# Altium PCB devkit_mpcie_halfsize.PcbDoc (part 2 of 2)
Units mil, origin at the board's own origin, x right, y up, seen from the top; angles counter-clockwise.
Board outline 1185.07 x 1313.97 mil, 4 copper layers (Top Layer, Mid-Layer 1, Mid-Layer 2, Bottom Layer), stack 34.6 mil thick; 83 components, 51 nets, 256 pads, 210 vias.
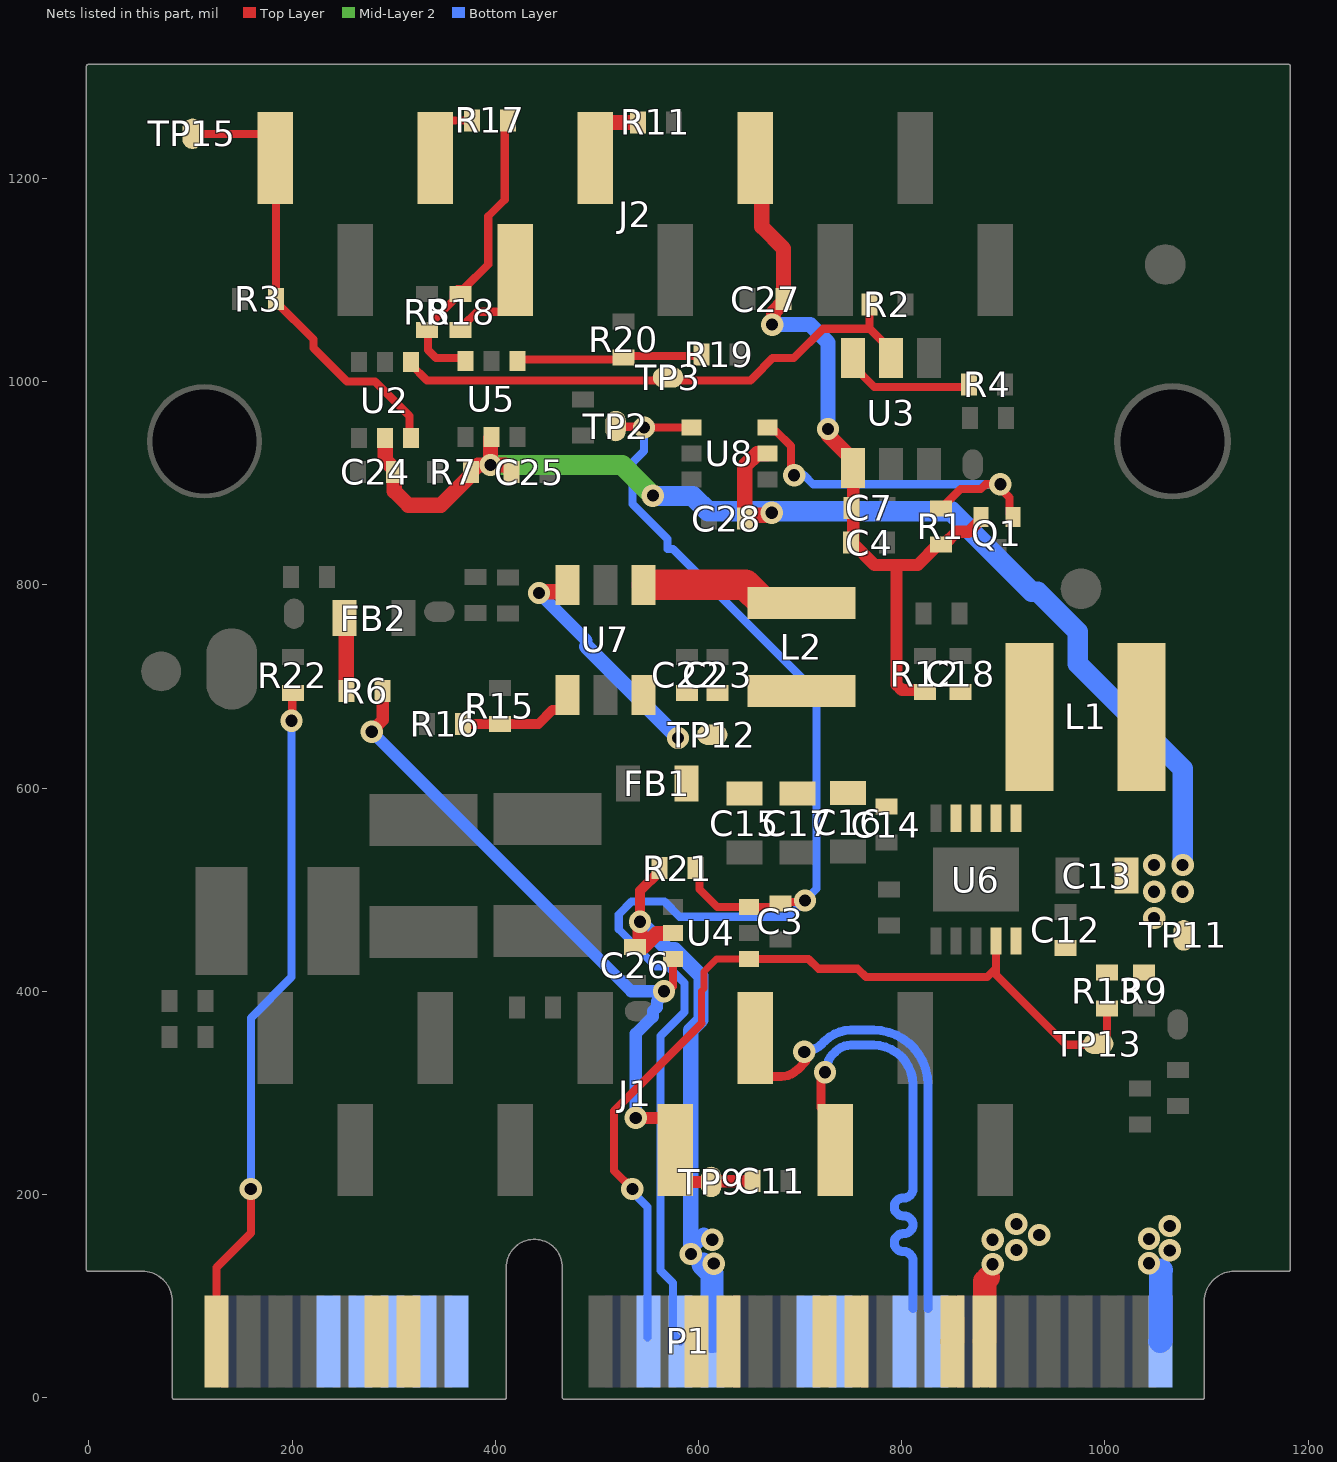
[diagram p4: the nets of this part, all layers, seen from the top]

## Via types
v1: diameter 22, hole 12, Top Layer to Bottom Layer, 210 vias

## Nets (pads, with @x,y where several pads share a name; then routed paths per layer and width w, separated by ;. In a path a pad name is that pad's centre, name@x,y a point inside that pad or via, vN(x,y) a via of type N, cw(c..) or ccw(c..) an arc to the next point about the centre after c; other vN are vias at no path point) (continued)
NetJ2_6: J2.6 R11.2 | length 67.8
  Top Layer w15: J2.6@498.23,1227.15 498.23,1251.35 502.09,1255.22 R11.2@540.21,1255.22
NetJ2_7: J2.7 R18.1 | length 97.9
  Top Layer w8: R18.1@365.85,1055.74 368.8,1055.74 381.89,1068.83 405.97,1068.83 419.49,1082.35 419.49,1094.89 J2.7@419.49,1109.91 ; J2.7@417.21,1112.19 419.49,1114.47 J2.7@419.49,1116.91
NetJ2_8: J2.8 R17.1 | length 27
  Top Layer w8: J2.8@350.19,1257.15 R17.1@377.18,1257.15
NetL1_2: L1.2 U6.1 U6.2
NetL2_2: L2.2 U7.1 | length 159.6
  Top Layer w30: U7.1@548.96,799.95 646.18,799.95 663.82,782.31 L2.2@701.22,782.31
NetQ1_1: Q1.1 R1.1 U8.6 | length 380.4
  Top Layer w8: U8.6@667.72,954.96 671.59,951.09 676.45,951.09 690.9,936.63 690.9,911.1 v1(694,908) ; R1.1@838.54,875.08 857.83,894.37 877.76,894.37 882.39,899 v1(897.03,899) 897.03,895.21 906.05,886.19 Q1.1@906.05,872.59 ; Q1.1@906.05,872.59 906.05,870.03 Q1.1@909.33,866.75 909.33,869.31 Q1.1@906.05,872.59
  Bottom Layer w8: v1(694,908) 703.85,908 712.85,899 v1(897.03,899)
NetR2_2: R2.2 TP3.1 U2.1 U3.5 | length 546.1
  Top Layer w8: U2.1@316.73,1019.18 316.73,1017.21 332.61,1001.33 TP3.1@558.81,1001.33 ; TP3.1@558.81,1004.19 TP3.1@558.81,1001.33 ; R2.2@768.21,1076.22 768.21,1052.57 768.73,1052.06 ; U3.5@789.54,1023.37 789.54,1031.24 768.73,1052.06 ; TP3.1@558.81,1001.33 651.02,1001.33 653.88,1004.19 672.88,1023.19 693.67,1023.19 722.54,1052.06 736.6,1052.06 768.73,1052.06
NetR4_2: R4.2 U3.6 | length 137.2
  Top Layer w8: U3.6@752.14,1027.5 750.39,1025.75 750.39,1017.25 772.95,994.69 863.68,994.69 R4.2@866.21,997.22
NetR8_2: R8.2 R17.2 R18.2 U5.3 | length 305.9
  Top Layer w8: U5.3@370.39,1020.17 367.37,1023.19 341.71,1023.19 333.66,1031.24 333.66,1050.22 R8.2@332.76,1051.12 335.71,1051.12 339.59,1054.99 339.59,1060.91 359.02,1080.34 359.02,1087.3 362.89,1091.18 368.8,1091.18 392.97,1115.34 392.97,1162.87 409.2,1179.09 409.2,1253.74 R17.2@412.61,1257.15
NetR15_1: R15.1 R16.2 U7.4 | length 125.1
  Top Layer w10: R16.2@368.18,663.15 442.44,663.15 456.28,676.99 464.16,676.99 470.97,683.8 U7.4@470.97,691.68 ; R15.1@401.38,663.05 R15.1@404.33,663.05 R15.1@407.28,663.05
NetR19_2: R19.2 R20.2 U5.1 | length 184.5
  Top Layer w8: U5.1@421.57,1020.17 423.39,1022 524.33,1022 R20.2@526.15,1023.82 ; R20.2@527.66,1025.34 530.79,1025.34 601.31,1025.34 R19.2@602.82,1026.85 ; R20.2@530.79,1022 R20.2@532.61,1023.82
ON_OFF: J2.10 R3.2 TP15.1 U2.6 | length 446.6
  Top Layer w8: TP15.1@101.83,1243.96 169.75,1243.96 183.27,1230.44 J2.10@183.27,1220.15 184.22,1219.19 184.22,1078.55 221.02,1041.76 221.02,1033.26 253.94,1000.34 281.41,1000.34 315.53,966.22 315.53,945.57 U2.6@316.73,944.38 ; J2.10@181.79,1238.37 J2.10@183.27,1239.85
PER0_N: P1.23
PER0_P: P1.25
PERST#: C3.1 P1.22 R21.1 TP2.1 U4.3 U8.1 | length 1429.7
  Top Layer w8: TP2.1@518.39,956.37 519.09,955.67 545.55,955.67 v1(546.25,954.96) U8.1@592.91,954.96 ; R21.1@597.06,521.26 600.94,517.39 600.94,500.43 618.41,482.96 U4.3@649.47,482.96 ; U4.3@658.23,482.75 676.67,482.75 C3.1@680.54,486.63 681.91,488 v1@706.05,488
  Bottom Layer w8: v1(546.25,954.96) 546.25,931.61 535,920.36 535,879.58 569.45,845.12 569.45,835.29 574.99,835.29 716.22,694.07 716.22,500.91 v1(704.68,489.37) 688.68,473.37 581.36,473.37 566.36,488.37 534.05,488.37 521.39,475.71 521.39,461.03 557.84,424.57 569.71,424.57 586,408.28 586,379.47 562.66,356.13 562.66,125.1 574.99,112.76 574.99,62.56 P1.22@582.07,55.49
PET0_N: P1.31
PET0_P: P1.33
REFCLK_N: P1.11
REFCLK_P: P1.13
SKY_USB_N: J1.8 P1.36 | length 423
  Top Layer w8.8: J1.8@720.5,285.37 720.5,310.99 cw(c733.76,310.99) v1(724.39,320.37)
  Bottom Layer w8.8: v1(724.39,320.37) ccw(c718.29,326.47) 726.91,326.47 cw(c742.27,326.47) 731.41,337.33 734.78,340.7 cw(c750,325.48) 750,347 772,347 cw(c772,308.06) 810.94,308.06 810.94,206 810.94,205.4 cw(c802.14,205.4) 802.14,196.6 801.37,196.6 ccw(c801.37,187.8) 792.57,187.8 ccw(c801.37,187.8) 801.37,179 802.14,179 cw(c802.14,170.2) 810.94,170.2 cw(c802.14,170.2) 802.14,161.4 801.37,161.4 ccw(c801.37,152.6) 792.57,152.6 ccw(c801.37,152.6) 801.37,143.8 802.14,143.8 cw(c802.14,135) 810.94,135 P1.36@810.94,88
SKY_USB_P: J1.7 P1.38 | length 438.1
  Top Layer w7.7: J1.7@654.39,316.12 J1.7@654.39,316.37 ; v1@705.5,330.98 ccw(c696.11,340.37) v1@709.39,340.37
  Top Layer w8.8: J1.7@669.39,316.12 681.08,316.12 ccw(c681.08,339.18) 697.38,322.86 v1@705.5,330.98
  Bottom Layer w7.7: v1(704.07,340.37) cw(c710.67,333.77) v1@710.67,343.11
  Bottom Layer w8.8: v1(704.07,340.37) cw(c710.17,334.27) 710.17,342.9 ccw(c710.17,357.1) 720.21,347.06 724.35,351.19 cw(c749.95,325.59) 749.95,361.8 772.1,361.8 cw(c772.1,308.16) 825.74,308.16 825.74,206 825.74,205.4 P1.38@825.74,88
SMB_CLK: P1.30
SMB_DATA: P1.32
UIM_CLK: P1.12
UIM_DATA: P1.10
UIM_PWR: P1.8
UIM_RESET: P1.14
UIM_VPP: P1.16
VCC_3V3: C12.1 C13.1 C24.1 C25.1 C26.1 C28.1 L1.1 P1.24 P1.39 P1.41 P1.52 R7.2 R9.2 R13.2 R21.2 TP11.1 U2.5 U4.5 U5.5 U6.10 U8.5 | length 1989.8
  Top Layer w10: v1(542.33,468.37) 542.33,499.01 561.63,518.31 R21.2@561.63,521.26
  Top Layer w15: U2.5@291.14,944.38 291.51,944 291.51,922.86 300.11,914.26 C24.1@300.11,911.31 300.48,910.93 300.48,892.28 314.27,878.5 346.41,878.5 376.04,908.13 R7.2@376.04,911.09 382.93,917.97 v1(395.26,917.97) ; U5.5@395.98,945.37 395.26,944.65 v1(395.26,917.97) ; C25.1@415.9,911.83 409.76,917.97 v1(395.26,917.97) ; v1(542.33,468.37) 542.41,468.29 542.41,443.7 542.49,443.63 545.44,443.63 558.81,457 574.29,457 U4.5@574.67,457.37 ; U8.5@667.72,929.37 667.34,929 657.54,929 645.38,916.83 645.38,865.46 C28.1@645.62,865.22 645.62,868.17 645.99,868.54 667.58,868.54 670.03,871 v1(671.93,871)
  Top Layer w23: P1.39@849.78,55.49 850.09,55.8 P1.39@850.09,77.37 ; P1.41@881.28,55.49 881.59,55.8 881.59,114.73 885.39,118.53
  Mid-Layer 2 w20: v1(395.26,917.97) 524.89,917.97 v1(555,887.86)
  Bottom Layer w15: v1(542.33,468.37) 569.63,441.07 576.54,441.07 602.5,415.12 602.5,371.85 592.39,361.74 v1(592.39,141.37) ; v1@593.73,148.71 v1@605.17,160.16
  Bottom Layer w20: v1(555,887.86) 555.38,887.48 594.17,887.48 609.28,872.37 848.58,872.37 927.73,793.21 933.84,793.21 973.14,753.91 973.14,722.52 1076.39,619.28 v1(1076.39,524.37)
  Bottom Layer w23: v1@604.39,131.37 613.25,122.51 613.25,55.8 P1.24@613.56,55.49 ; P1.52@1054.51,55.49 1054.82,55.8 1054.82,124.8 1055.39,125.37
  other v1: 889.39,131.37 615,132 1043.39,132.37 912.77,145.38 1063.69,145 613.39,155.43 889.39,155.43 1043.39,156.35 935.25,160.16 1063.69,169 912.77,171 1048.39,472.12 1048.39,498 1076.39,498 1048.39,524.37
VCC_4V0: C4.1 C7.1 C14.1 C15.1 C16.1 C17.1 C18.2 C22.1 C23.1 C27.1 FB1.1 J2.4 L2.1 Q1.2 R1.2 R12.2 TP12.1 U3.1 U6.3 U6.4 U7.3 U7.6 | length 990.5
  Top Layer w12: U3.1@752.14,915.1 752.14,840.68 773.12,819.7 794.38,819.7 ; R12.2@822.97,694.69 821.1,696.56 800.11,696.56 794.95,701.72 794.95,819.12 794.38,819.7 ; Q1.2@877.83,866.75 877.83,864.19 865.96,852.32 854.16,852.32 841.49,839.65 R1.2@838.54,839.65 835.59,839.65 815.64,819.7 794.38,819.7
  Top Layer w15: v1(443,792) 444.34,793.34 466.66,793.34 470.97,797.65 U7.3@470.97,799.95 U7.3@468.66,797.64 ; J2.4@655.71,1220.15 662.19,1213.67 662.19,1152.57 683.65,1131.11 C27.1@683.65,1081.22 683.65,1078.26 673.73,1068.35 673.73,1057.53 v1(672.39,1056.19) ; v1(727.39,953.37) 727.39,947.73 752.14,922.98 U3.1@752.14,915.1
  Bottom Layer w12: v1(443,792) 489.8,745.2 489.8,739.26
  Bottom Layer w15: 489.8,739.26 v1(579.81,649.25) ; v1(672.39,1056.19) 709.87,1056.19 727.39,1038.67 v1(727.39,953.37)
VCC_5V0: FB2.2 R6.2 | length 72.4
  Top Layer w15: FB2.2@251.43,767.22 253.32,765.32 253.32,696.16 R6.2@253.7,695.78
VCC_VUSB: C11.1 J1.6 R6.1 TP9.1 U4.6 | length 777.1
  Top Layer w8: v1(566,400) 569.79,400 574.47,404.69 574.67,404.69 U4.6@574.67,431.78
  Top Layer w12: v1(278.3,655.4) 278.3,656.13 289.13,666.96 R6.1@289.13,695.78 ; v1(538.19,275.37) 565.62,275.37 577.14,263.85 J1.6@577.14,243.84 577.14,223.89 588.66,212.37 TP9.1@612.39,212.37 612.96,212.95 652.53,212.95 C11.1@653.11,213.52
  Bottom Layer w12: v1(278.3,655.4) 533.7,400 v1(566,400) 566,397.29 559,390.29 559,384.29 555,380.29 555,375 538.19,358.19 v1(538.19,275.37)
W_DISABLE#: P1.20 R13.1 TP13.1 U4.1 U6.9 | length 915.7
  Top Layer w7: 602.82,368.29 602.82,400.23 605.42,402.83 605.42,419.45 617.76,431.78 U4.1@649.47,431.78
  Top Layer w8: v1(534.82,205.4) 516.86,223.36 516.86,282.33 602.82,368.29 ; U4.1@649.47,431.78 708.35,431.78 717.98,422.16 756.5,422.16 764.65,414.01 884.09,414.01 892.63,422.54 ; U6.9@892.63,449.49 892.63,422.54 ; R13.1@1001.85,382.98 1001.85,356.83 1000.68,355.67 1000.68,353.91 995.14,348.37 TP13.1@993.39,348.37 992.39,347.37 961.53,347.37 892.63,416.27 892.63,422.54
  Bottom Layer w8: v1(534.82,205.4) 534.82,202.55 549.66,187.71 P1.20@549.66,59.32
WAKE: P1.1 R22.2 | length 669.3
  Top Layer w8: P1.1@125.37,55.49 125.37,128.33 159.29,162.24 v1(159.29,205.4) ; v1(199.39,666.2) 200.04,666.86 200.04,692.92 R22.2@200.7,693.57
  Bottom Layer w8: v1(159.29,205.4) 159.29,373.87 199.39,413.97 v1(199.39,666.2)
pads on no net: Fiducial1.Fiducial Fiducial2.Fiducial Fiducial3.Fiducial J1.2 J1.3 J2.2 J2.9 P1.2 P1.6 P1.17 P1.19 P1.28 P1.45 P1.47 P1.48 P1.49 P1.51 U2.4 U6.5 U6.8 U8.4

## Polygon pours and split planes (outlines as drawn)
GND on Top Layer "GND_L01_P042" (solid, remove dead copper, pour order 42): 0.19,1307.84 1181.19,1307.84 1181.19,123.82 1127.16,123.82 ccw(c1127.16,92.84) 1096.19,92.84 cw(c1081.19,92.84) 1081.19,77.84 507.19,77.84 cw(c507.19,115.84) 469.19,115.84 469.19,124.71 ccw(c438.19,124.71) 438.19,155.71 ccw(c438.19,127.71) 410.19,127.71 410.19,97.84 cw(c390.19,97.84) 390.19,77.84 100.19,77.84 cw(c100.19,92.84) 85.19,92.84 ccw(c54.14,92.84) 54.14,123.88 50.19,123.88 0.19,123.82
VCC_3V3 on Top Layer "VCC_3V3_L01_P020" (solid, pour order 20): 1012.04,737.74 1012.04,566.95 992.14,547.06 992.14,484.06 972.42,464.34 909.42,464.34 907.42,462.34 907.42,439.34 935.39,411.37 1090.96,411.37 1094.47,414.88 1093.94,652.48 1059.39,739.4
NetC20_1 on Top Layer "NETC20_1_L01_P002" (solid, pour order 2): 298.87,784.62 459.4,784.62 517.91,726.1 517.91,676.14 482.32,711.74 450.03,711.74 433.15,694.87 361.13,694.87 298.87,757.12
NetL2_2 on Top Layer "NETL2_2_L01_P000" (solid, pour order 0): 556.83,828.8 707.7,828.8 746.88,789.62 723.5,766.25 648.6,766.25 634.31,780.54 556.33,780.54 541.23,805.13
VCC_4V0 on Top Layer "VCC_4V0_L01_P004" (solid, pour order 4): 877.84,571.25 877.83,686.72 847.42,710.88 534.82,710.88 534.82,675.37 575.65,604.46 600.63,569.37 806.67,569.37 822.92,586.43 844.22,586.31 850.04,571.25
NetC5_1 on Top Layer "NETC5_1_L01_P014" (solid, pour order 14): 139.39,305.37 104.39,340.37 104.39,572.54 168.21,636.37 351.1,636.37 526.15,636.37 539.36,618.12 539.36,575.38 501.35,537.37 214.39,537.37 200.39,523.37 200.39,305.37
NetL1_2 on Top Layer "NETL1_2_L01_P016" (solid, pour order 16): 950.2,692.91 950.2,579.96 931.75,568.49 886.87,568.49 886.87,594.17 924.14,696.63 941.64,714.05
VCC_3V3 on Top Layer "VCC_3V3_L01_P012" (solid, pour order 12): 891.39,81.37 848.39,81.37 838.39,91.37 838.39,122.37 852.4,138.73 889.76,182.37 921.87,182.37 941.54,162.71 941.54,149.77 891.45,99.69
GND on Bottom Layer "GND_L04_P040" (solid, remove dead copper, pour order 40): 0,1308.15 1181,1308.15 1181,124.13 1126.98,124.13 ccw(c1126.98,93.15) 1096,93.15 cw(c1081,93.15) 1081,78.15 507,78.15 cw(c507,116.15) 469,116.15 469,125.02 ccw(c438,125.02) 438,156.02 ccw(c438,128.02) 410,128.02 410,98.15 cw(c390,98.15) 390,78.15 100,78.15 cw(c100,93.15) 85,93.15 ccw(c53.96,93.15) 53.96,124.19 50,124.19 0,124.13
no net on Bottom Layer "NONET_L04_P046" (solid, pour order 46): -4423.12,-4763
VCC_3V3 on Bottom Layer "VCC_3V3_L04_P032" (solid, pour order 32): 1063.39,90.37 1076.39,103.37 1076.39,175.33 1068.71,183 1048.39,183 1024,158.61 1024,133.64 1043.39,114.25 1043.39,81.37 1049.39,75.37
VCC_3V3 on Bottom Layer "VCC_3V3_L04_P028" (solid, pour order 28): 618.39,172.37 587.39,172.37 575.39,160.37 575.39,132.37 597.39,110.37 625.39,110.37 628.39,113.37 628.39,162.37
GND on Mid-Layer 1 "GND_L02_P036" (solid, pour order 36): -0.61,1310.37 1180.39,1310.37 1180.39,126.35 1126.36,126.35 ccw(c1126.36,95.37) 1095.39,95.37 cw(c1080.39,95.37) 1080.39,80.37 506.39,80.37 cw(c506.39,118.37) 468.39,118.37 468.39,127.24 ccw(c437.39,127.24) 437.39,158.24 ccw(c437.39,130.24) 409.39,130.24 409.39,100.37 cw(c389.39,100.37) 389.39,80.37 99.39,80.37 cw(c99.39,95.37) 84.39,95.37 ccw(c53.34,95.37) 53.34,126.41 49.39,126.41 -0.61,126.35
VCC_3V3 on Mid-Layer 1 "VCC_3V3_L02_P034" (solid, pour order 34): 1090.99,154.15 1050.22,113.37 593.39,113.37 577.39,129.37 577.39,166.94 594.45,184 769.02,184 869.39,284.37 869.39,399.88 979.3,509.79 1003.82,537.37 1090.99,537.37
GND on Mid-Layer 2 "GND_L03_P038" (solid, pour order 38): -0.61,1310.37 1180.39,1310.37 1180.39,126.35 1126.36,126.35 ccw(c1126.36,95.37) 1095.39,95.37 cw(c1080.39,95.37) 1080.39,80.37 506.39,80.37 cw(c506.39,118.37) 468.39,118.37 468.39,127.24 ccw(c437.39,127.24) 437.39,158.24 ccw(c437.39,130.24) 409.39,130.24 409.39,100.37 cw(c389.39,100.37) 389.39,80.37 99.39,80.37 cw(c99.39,95.37) 84.39,95.37 ccw(c53.34,95.37) 53.34,126.41 49.39,126.41 -0.61,126.35

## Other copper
Top Layer:
  pour cut-out: 957.78,575.37 961.53,575.37 939.69,553.53 919.55,553.53
  pour cut-out: 1012.04,570.16 950.2,570.16 950.2,750.96 1012.04,750.96
  pour cut-out: 637.63,711.75 637.63,761.4 642.48,766.25 764.81,766.25 764.81,711.75
  pour cut-out: 362.85,77 362.85,105.76 395.55,105.76
  pour cut-out: 1055.57,105.76 1088,105.76 1088,93 1054.39,93
  pour cut-out: 678.23,1170.07 690.93,1157.37 720.69,1157.37
  pour cut-out: 813.09,721.68
Bottom Layer:
  pour cut-out: 95.44,76.75 95.44,105.52 128.15,105.52
  pour cut-out: 506,76.89 506,105.39 473.59,105.39
  pour cut-out: 363.44,77 363.44,105.76 396.15,105.76

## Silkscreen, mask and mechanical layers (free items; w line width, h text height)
Top Overlay:
  drawing of 1300 lines, arcs and shapes, not listed
  text "1002580REVA" at 58.39,162.37 h30 r90
Mechanical 2 - Board Outline:
  lines w3.94: -0.61,126.35 -0.61,1310.37 ; -0.61,126.35 52.54,126.35 ; -0.61,126.35 -0.61,1310.37 ; -0.61,126.35 52.54,126.35 ; -0.61,1310.37 1180.49,1310.37 ; -0.61,1310.37 1180.49,1310.37 ; 52.54,126.35 cw(c52.54,94.86) 84.03,94.86 ; 52.54,126.35 cw(c52.54,94.86) 84.03,94.86 ; 84.03,0.37 84.03,94.86 ; 84.03,0.37 408.84,0.37 ; 84.03,0.37 408.84,0.37 ; 84.03,0.37 84.03,94.86 ; 408.84,0.37 408.84,128.32 ; 408.84,0.37 408.84,128.32 ; 408.84,128.32 cw(c438.36,128.32) 467.89,128.32 ; 408.84,128.32 cw(c438.36,128.32) 467.89,128.32 ; 467.89,0.37 467.89,128.32 ; 467.89,0.37 1095.84,0.37 ; 467.89,0.37 467.89,128.32 ; 467.89,0.37 1095.84,0.37 ; 1095.84,0.37 1095.84,94.86 ; 1095.84,0.37 1095.84,94.86 ; 1095.84,94.86 cw(c1127.34,94.86) 1127.34,126.35 ; 1095.84,94.86 cw(c1127.34,94.86) 1127.34,126.35 ; 1127.34,126.35 1180.49,126.35 ; 1127.34,126.35 1180.49,126.35 ; 1180.49,126.35 1180.49,1310.37 ; 1180.49,126.35 1180.49,1310.37
Drill Drawing:
  drawing of 1074 lines, arcs and shapes, not listed
  text "Symbol" at 10597.5,5502.5 h72
  text "Count" at 11103.38,5502.5 h72
  text "Hole Size" at 11693.22,5502.5 h72
  text "Plated" at 12842.88,5502.5 h72
  text "Hole Type" at 13348.76,5502.5 h72
  text "Drill Layer Pair" at 14082.56,5502.5 h72
  text "Via/Pad" at 15582.11,5502.5 h72
  text "Pad Shape" at 16171.96,5502.5 h72
  text "Template" at 16917.76,5502.5 h72
  text "Description" at 17567.59,5502.5 h72
  text "Hole Tolerance (+)" at 18421.35,5502.5 h72
  text "Hole Tolerance (-)" at 19754.96,5502.5 h72
  text "2" at 11103.38,5352.5 h60
  text "2.600mm (102.36mil)" at 11693.22,5352.5 h60
  text "PTH" at 12842.88,5352.5 h60
  text "Round" at 13348.76,5352.5 h60
  text "Top Layer - Bottom Layer" at 14082.56,5352.5 h60
  text "Pad" at 15582.11,5352.5 h60
  text "Rounded" at 16171.96,5352.5 h60
  text "(Mixed)" at 16917.76,5352.5 h60
  text "210" at 11103.38,5202.5 h60
  text "0.305mm (12.00mil)" at 11693.22,5202.5 h60
  text "PTH" at 12842.88,5202.5 h60
  text "Round" at 13348.76,5202.5 h60
  text "Top Layer - Bottom Layer" at 14082.56,5202.5 h60
  text "Via" at 15582.11,5202.5 h60
  text "Rounded" at 16171.96,5202.5 h60
  text "v56h30" at 16917.76,5202.5 h60
  text "212 Total" at 11103.38,5052.5 h60
  text "Layer" at 10577.5,4657.5 h60
  text "Name" at 10987.41,4657.5 h60
  text "Material" at 11917.16,4657.5 h60
  text "Thickness" at 12776.92,4657.5 h60
  text "Constant" at 13426.76,4657.5 h60
  text "Board Layer Stack" at 13996.62,4657.5 h60
  text "Top Overlay" at 10987.41,4537.5 h60
  text "Top Solder" at 10987.41,4417.5 h60
  text "Solder Resist" at 11917.16,4417.5 h60
  text "1.00mil" at 12776.92,4417.5 h60
  text "3.5" at 13426.76,4417.5 h60
  text "1" at 10577.5,4297.5 h60
  text "Top Layer" at 10987.41,4297.5 h60
  text "Copper" at 11917.16,4297.5 h60
  text "0.60mil" at 12776.92,4297.5 h60
  text "Dielectric 1" at 10987.41,4177.5 h60
  text "FR-4" at 11917.16,4177.5 h60
  text "8.00mil" at 12776.92,4177.5 h60
  text "4.5" at 13426.76,4177.5 h60
  text "2" at 10577.5,4057.5 h60
  text "Mid-Layer 1" at 10987.41,4057.5 h60
  text "Copper" at 11917.16,4057.5 h60
  text "1.20mil" at 12776.92,4057.5 h60
  text "Dielectric2" at 10987.41,3937.5 h60
  text "FR-4" at 11917.16,3937.5 h60
  text "15.00mil" at 12776.92,3937.5 h60
  text "4.5" at 13426.76,3937.5 h60
  text "3" at 10577.5,3817.5 h60
  text "Mid-Layer 2" at 10987.41,3817.5 h60
  text "Copper" at 11917.16,3817.5 h60
  text "1.20mil" at 12776.92,3817.5 h60
  text "Dielectric3" at 10987.41,3697.5 h60
  text "FR-4" at 11917.16,3697.5 h60
  text "8.00mil" at 12776.92,3697.5 h60
  text "4.5" at 13426.76,3697.5 h60
  text "4" at 10577.5,3577.5 h60
  text "Bottom Layer" at 10987.41,3577.5 h60
  text "Copper" at 11917.16,3577.5 h60
  text "0.60mil" at 12776.92,3577.5 h60
  text "Bottom Solder" at 10987.41,3457.5 h60
  text "Solder Resist" at 11917.16,3457.5 h60
  text "1.00mil" at 12776.92,3457.5 h60
  text "3.5" at 13426.76,3457.5 h60
  text "Bottom Overlay" at 10987.41,3337.5 h60
  text "Fiducial" at 8804.39,3025.37 h37
  text "350 mil scrap rail" at 230.18,2983.37 h37
  text "350 mil scrap rail" at 1650.98,2969.37 h37
  text "350 mil scrap rail" at 3032.08,2969.37 h37
  text "350 mil scrap rail" at 4413.18,2969.37 h37
  text "350 mil scrap rail" at 5794.29,2969.37 h37
  text "350 mil scrap rail" at 7175.39,2969.37 h37
  text "350 mil scrap rail" at 8553.39,2928.37 h37
  text "100 Mil spacing, routed" at 1533.39,2758.37 h37
  text "100 Mil spacing, routed" at 2914.49,2758.37 h37
  text "100 Mil spacing, routed" at 4295.6,2758.37 h37
  text "100 Mil spacing, routed" at 5676.7,2758.37 h37
  text "100 Mil spacing, routed" at 7057.8,2758.37 h37
  text "100 Mil spacing, routed" at 8438.91,2758.37 h37
  text "100 Mil spacing, routed" at 188.18,2753.37 h37
  text "Copy Artwork" at 203.18,2333.37 h60
  text "Copy Artwork" at 1623.98,2319.37 h60
  text "Copy Artwork" at 3005.08,2319.37 h60
  text "Copy Artwork" at 4386.18,2319.37 h60
  text "Copy Artwork" at 5767.29,2319.37 h60
  text "Copy Artwork" at 7148.39,2319.37 h60
  text "Copy Artwork" at 8529.49,2319.37 h60
  text "NOTES:" at 10466.39,2133.37 h56.25
  text "Board is rotated" at 115.39,2074.37 h60
  text "Board is rotated" at 1536.18,2060.37 h60
  text "Board is rotated" at 2917.29,2060.37 h60
  text "Board is rotated" at 4298.39,2060.37 h60
  text "Board is rotated" at 5679.49,2060.37 h60
  text "Board is rotated" at 7060.6,2060.37 h60
  text "Board is rotated" at 8441.7,2060.37 h60
  text "1. BOARD IS A 2x7 ARRAY. SEE PANEL ARTWORK LAYER FOR PANEL DETAIL." at 10466.39,2027.37 h56.25
  text "180 degrees" at 129.18,1961.37 h60
  text "180 degrees" at 1549.98,1947.37 h60
  text "180 degrees" at 2931.08,1947.37 h60
  text "180 degrees" at 4312.18,1947.37 h60
  text "180 degrees" at 5693.29,1947.37 h60
  text "180 degrees" at 7074.39,1947.37 h60
  text "180 degrees" at 8455.49,1947.37 h60
  text "2. BOARD TO BE SCORED AT DESIGNATED LINES. SCORING TO BE 30 DEG." at 10466.39,1913.23 h56.25
  text "3. BOARD TO USE Tg 170C OR GREATER." at 10466.39,1804.37 h56.25
  text "4. BOARD THICKNESS TOLERANCE +/- 10%." at 10466.39,1684.94 h56.25
  text "5) BOARD TO USE GREEN SOLDER MASK." at 10466.39,1570.8 h56.25
  text "250 mill scrap rail" at -102.61,1473.37 h37 r270
  text "6) BOARD TO USE WHITE SILK SCREEN." at 10466.39,1456.66 h56.25
  text "100 Mil spacing, routed" at 135.39,1350.37 h37
  text "7) FOUR LAYER BOARD." at 10466.39,1342.51 h56.25
  text "100 Mil spacing, routed" at 1556.18,1336.37 h37
  text "100 Mil spacing, routed" at 2937.29,1336.37 h37
  text "100 Mil spacing, routed" at 4318.39,1336.37 h37
  text "100 Mil spacing, routed" at 5699.49,1336.37 h37
  text "100 Mil spacing, routed" at 7080.6,1336.37 h37
  text "100 Mil spacing, routed" at 8461.7,1336.37 h37
  text "8) BOARD TO USE ENIG SURFACE FINISH." at 10466.39,1228.37 h56.25
  text "9) INNER COPPER LAYERS TO BE 1 OZ COPPER. OUTER COPPER LAYERS TO BE 0.5 OZ COPPER." at 10462.39,1112.96 h56.25
  text "10) MIN HOLE WALL THICKNESS 1 mil" at 10469,997.55 h56.25
  text "Copy Artwork" at 1632.98,911.37 h60
  text "Copy Artwork" at 3014.08,911.37 h60
  text "Copy Artwork" at 4395.18,911.37 h60
  text "Copy Artwork" at 5776.29,911.37 h60
  text "Copy Artwork" at 7157.39,911.37 h60
  text "Copy Artwork" at 8538.49,911.37 h60
  text "11) BOARD TO USE 1OZ PLATING THICKNESS (1.2 mil +/-10%)." at 10469,882.14 h56.25
  text "12) mPCIe card edge to have 0.25mm card edge bevel at 45 degrees. See PCI EXPRESS MINI CARD ELECTROMECHANICAL SPECIFICATION, REVISION 1.2 figure 2-6." at 10464,777.14 h56.25
  text "13) Hard Gold thickness shall be 30 micro-inches over edge finger tabs." at 10464,663.14 h56.25
  text "See Note 12" at 153.85,572.37 h60
  text "200 mill scrap rail" at 1302.39,510.37 h37 r90
  text "200 mill scrap rail" at 2683.49,510.37 h37 r90
  text "200 mill scrap rail" at 4064.6,510.37 h37 r90
  text "200 mill scrap rail" at 5445.7,510.37 h37 r90
  text "200 mill scrap rail" at 6826.8,510.37 h37 r90
  text "200 mill scrap rail" at 8207.91,510.37 h37 r90
  text "250 mill scrap rail" at 9589.01,510.37 h37 r90
  text "Hard Gold" at 190.39,201.37 h60
  text "100 Mil spacing, routed" at 135.39,-59.63 h37
  text "100 Mil spacing, routed" at 1556.18,-73.63 h37
  text "100 Mil spacing, routed" at 2937.29,-73.63 h37
  text "100 Mil spacing, routed" at 4318.39,-73.63 h37
  text "100 Mil spacing, routed" at 5699.49,-73.63 h37
  text "100 Mil spacing, routed" at 7080.6,-73.63 h37
  text "100 Mil spacing, routed" at 8461.7,-73.63 h37
  text "350 mil scrap rail" at 8532.39,-201.63 h37
  text "350 mil scrap rail" at 222.39,-289.63 h37
  text "350 mil scrap rail" at 1643.18,-303.63 h37
  text "350 mil scrap rail" at 3024.29,-303.63 h37
  text "350 mil scrap rail" at 4405.39,-303.63 h37
  text "350 mil scrap rail" at 5786.49,-303.63 h37
  text "350 mil scrap rail" at 7167.6,-303.63 h37
  text "Fiducial" at 8863.39,-346.63 h37
  text "Fiducial" at 346.39,-371.63 h37
  text "Vscore" at -179.61,-631.63 h37
  text "Vscore" at 9466.01,-634.63 h37
  text "Vscore" at 2545.92,-641.02 h37
  text "Vscore" at 8075.92,-641.02 h37
  text "Vscore" at 1161.39,-641.63 h37
  text "Vscore" at 3904.92,-644.02 h37
  text "Vscore" at 6699.92,-644.02 h37
  text "Vscore" at 5296.92,-659.02 h37
  text "-routed cutouts should cut 30 mil into scrap rails" at -20.61,-962.63 h37

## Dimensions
184.79,20.03 to 94,136 on Drill Drawing
1029.01,15.36 to 913.04,106.14 on Drill Drawing
132.34,-356.78 to 304.45,-359.42 on Drill Drawing
9255.39,3038.37 to 9083.28,3041 on Drill Drawing
9314.39,-333.63 to 9142.28,-331 on Drill Drawing
8294.87,-496.66 to 8385.66,-612.63 on Drill Drawing
8095.17,-496.66 to 8004.39,-612.63 on Drill Drawing
8294.87,-496.66 to 8385.66,-612.63 on Drill Drawing
8095.17,-496.66 to 8004.39,-612.63 on Drill Drawing
6918.87,-499.66 to 7009.66,-615.63 on Drill Drawing
6719.17,-499.66 to 6628.39,-615.63 on Drill Drawing
6918.87,-499.66 to 7009.66,-615.63 on Drill Drawing
6719.17,-499.66 to 6628.39,-615.63 on Drill Drawing
5515.87,-514.66 to 5606.66,-630.63 on Drill Drawing
5316.17,-514.66 to 5225.39,-630.63 on Drill Drawing
5515.87,-514.66 to 5606.66,-630.63 on Drill Drawing
5316.17,-514.66 to 5225.39,-630.63 on Drill Drawing
4123.87,-499.66 to 4214.66,-615.63 on Drill Drawing
3924.17,-499.66 to 3833.39,-615.63 on Drill Drawing
4123.87,-499.66 to 4214.66,-615.63 on Drill Drawing
3924.17,-499.66 to 3833.39,-615.63 on Drill Drawing
2764.87,-496.66 to 2855.66,-612.63 on Drill Drawing
2565.17,-496.66 to 2474.39,-612.63 on Drill Drawing
2764.87,-496.66 to 2855.66,-612.63 on Drill Drawing
2565.17,-496.66 to 2474.39,-612.63 on Drill Drawing
-4.36,-462.99 to -95.14,-578.96 on Drill Drawing
9468.97,-471.77 to 9559.75,-587.74 on Drill Drawing
804.64,48.01 to 713.86,163.98 on Drill Drawing
225.75,43.62 to 316.53,159.59 on Drill Drawing
-0.61,1310.37 to 1180.49,1310.37 on Mechanical 13
1095.84,0.37 to 1180.49,1310.37 on Mechanical 13
1180.64,-497.27 to 1089.86,-613.24 on Drill Drawing
1380.34,-497.27 to 1471.13,-613.24 on Drill Drawing
1180.64,-497.27 to 1089.86,-613.24 on Drill Drawing
1380.34,-497.27 to 1471.13,-613.24 on Drill Drawing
